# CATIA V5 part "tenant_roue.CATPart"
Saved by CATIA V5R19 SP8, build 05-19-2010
Part number: Part2
Bounding box of the stored display mesh (mm): x 0 to 130, y 0 to 85, z 0 to 90
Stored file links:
  G:\EU_thinkMotion\CFAO_2010\SIL_groupe2\SIL_groupe2\A reprendre\fnongaibaa\fnongaibaa\tenant_roue.CATPart
  C:\Users\Fabien\Desktop\catia\tenant roue.CATPart
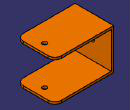
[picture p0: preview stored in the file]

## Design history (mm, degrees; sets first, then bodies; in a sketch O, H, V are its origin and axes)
Body1 (main body)
  Sketch1 on yz-plane, origin (0, 0, 0), H (0, 1, 0), V (0, 0, 1)
    line L1 (0, 0) -> (85, 0)
    line L2 (85, 0) -> (85, 90)
    line L3 (85, 90) -> (0, 90)
    line L4 (0, 90) -> (0, 0)
    length L2 = 90
    length L3 = 85
    horizontal: L1 H, L3 H
    vertical: L2 V, L4 V
  Pad1: profile Sketch1, direction (1, 0, 0), length 5
  Sketch2 on end face of Pad1, origin (5, 0, 0), H (0, 1, 0), V (0, 0, 1)
    line L1 (0, 5) -> (85, 5)
    line L2 (85, 5) -> (85, 0)
    line L3 (85, 0) -> (0, 0)
    line L4 (0, 0) -> (0, 5)
    line L5 (0, 90) -> (85, 90)
    line L6 (85, 90) -> (85, 85)
    line L7 (85, 85) -> (0, 85)
    line L8 (0, 85) -> (0, 90)
    reference projected line E1 (0, 0) -> (85, 0) from edge [face of Pad1 from Sketch1.L1 | end face of Pad1]
    reference projected line E2 (85, 0) -> (85, 90) from edge [face of Pad1 from Sketch1.L2 | end face of Pad1]
    reference projected line E3 (0, 90) -> (0, 0) from edge [face of Pad1 from Sketch1.L4 | end face of Pad1]
    reference projected line E4 (85, 90) -> (0, 90) from edge [face of Pad1 from Sketch1.L3 | end face of Pad1]
    reference projected line E5 (85, 0) -> (85, 90) from edge [face of Pad1 from Sketch1.L2 | end face of Pad1]
    reference projected line E6 (0, 90) -> (0, 0) from edge [face of Pad1 from Sketch1.L4 | end face of Pad1]
    length L6 = 5
    length L2 = 5
    horizontal: L1 H, L3 H, L5 H, L7 H
    vertical: L2 V, L4 V, L6 V, L8 V
    coincidence: L3 E1, L2 E2, E3 L4, L5 E4, L6 E5, L8 E6
  Pad2: profile Sketch2, direction (1, 0, 0), length 125
  Fillet1: radius 15, on edge [face of Pad2 | end face of Pad2] (x4)
  Sketch3 on face of Pad2, origin (84.966, 55.6835, 90), H (1, 0, 0), V (0, 1, 0)
    point P1 (25.034, -13.1835)
    axis line L1 (110, -13.1835) -> (-110, -13.1835)
    reference projected line E1 (-84.966, 29.3165) -> (-79.966, 29.3165) from edge [face of Pad2 | face of Pad2]
    reference projected line E2 (-84.966, -55.6835) -> (-79.966, -55.6835) from edge [face of Pad2 | face of Pad2]
    reference projected line E3 (45.034, 29.3165) -> (45.034, -55.6835) from edge [face of Pad2 | end face of Pad2]
    distance P1 E3 = 20
    horizontal: L1 H
    symmetry: E1 E2 L1
    coincidence: P1 L1
  Hole1: placed by Sketch3, at (110, 42.5, 90) direction (0, 0, -1), diameter 10, through (limit type 3)
  Sketch4 on start face of Pad1, origin (0, 51.0252, 48.0326), H (0, 1, 0), V (0, 0, -1)
    point P1 (-8.5252, 3.0326)
    reference projected line E1 (33.9748, 48.0326) -> (33.9748, -41.9674) from edge [start face of Pad1 | face of Pad2]
    reference projected line E2 (-51.0252, -41.9674) -> (-51.0252, 48.0326) from edge [start face of Pad1 | face of Pad2]
    reference projected line E3 (33.9748, -41.9674) -> (-51.0252, -41.9674) from edge [start face of Pad1 | face of Pad2]
    reference projected line E4 (-51.0252, 48.0326) -> (33.9748, 48.0326) from edge [start face of Pad1 | face of Pad2]
    equidistance: E1 E2 P1, E3 E4 P1
  Hole2: placed by Sketch4, at (0, 42.5, 45) direction (1, 0, 0), diameter 10, through (limit type 6)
